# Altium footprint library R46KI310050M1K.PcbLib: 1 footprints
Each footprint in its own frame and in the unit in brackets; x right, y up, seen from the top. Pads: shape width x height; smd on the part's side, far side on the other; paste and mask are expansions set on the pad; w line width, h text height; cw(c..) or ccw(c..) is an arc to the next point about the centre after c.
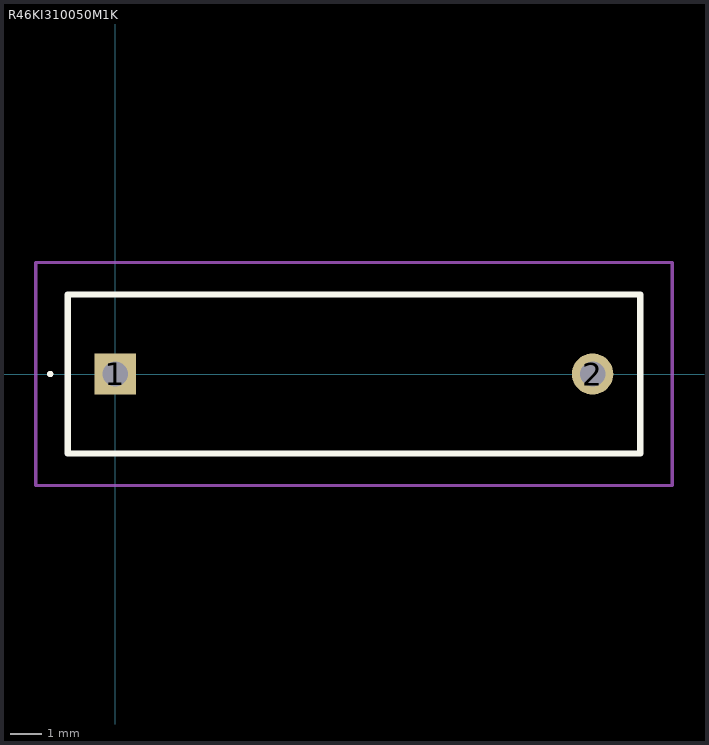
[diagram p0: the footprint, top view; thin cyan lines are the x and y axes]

## R46KI310050M1K [mm]
pads (2):
  rect 1.3x1.3 hole 0.8: 1(0,0)
  round 1.3 hole 0.8: 2(15,0)
Top Overlay:
  lines w0.1: -2.1,0 cw(c-2.05,0) -2,0 ; -2.1,0 -2.1,0 ; -2.1,0 ccw(c-2.05,0) -2,0 ; -2,0 -2,0
  lines w0.2: -1.5,-2.5 16.5,-2.5 16.5,2.5 -1.5,2.5 -1.5,-2.5
Mechanical 15:
  lines w0.1: -1.5,-2.5 16.5,-2.5 16.5,2.5 -1.5,2.5 -1.5,-2.5
Mechanical 20:
  lines w0.1: -2.5,-3.5 17.5,-3.5 17.5,3.5 -2.5,3.5 -2.5,-3.5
